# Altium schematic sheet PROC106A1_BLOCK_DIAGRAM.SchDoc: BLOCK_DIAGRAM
size 431 x 279 mm; Date: Not shown in title block; ApprovedBy: Not shown in title block; CheckedBy: Not shown in title block; Author: Not shown in title block; CompanyName: Not shown in title block; DrawnBy: Antony/Anand Ram; Engineer: Not shown in title block; Organization: Not shown in title block; Address1: Not shown in title block; Address2: Not shown in title block; Address3: Not shown in title block; Address4: Not shown in title block; DocumentNumber: 1; Revision: Use project parameter SCH_Rev; SheetNumber: 1; SheetTotal: 12; PageSetup: Record=PageOptions¦CenterHorizontal=True¦CenterVertical=True¦PrintScale=1.00¦XCorrection=1.00¦YCorrection=1.00¦PrintKind=0¦BorderSize=5000000¦LeftOffset=0¦BottomOffset=0¦Orientation=2¦PaperLength=1000¦PaperWidth=1000¦Scale=100¦PaperSource=15¦PrintQuality=600¦MediaType=1¦DitherType=10¦PaperKind=Letter¦PrintScaleMode=1
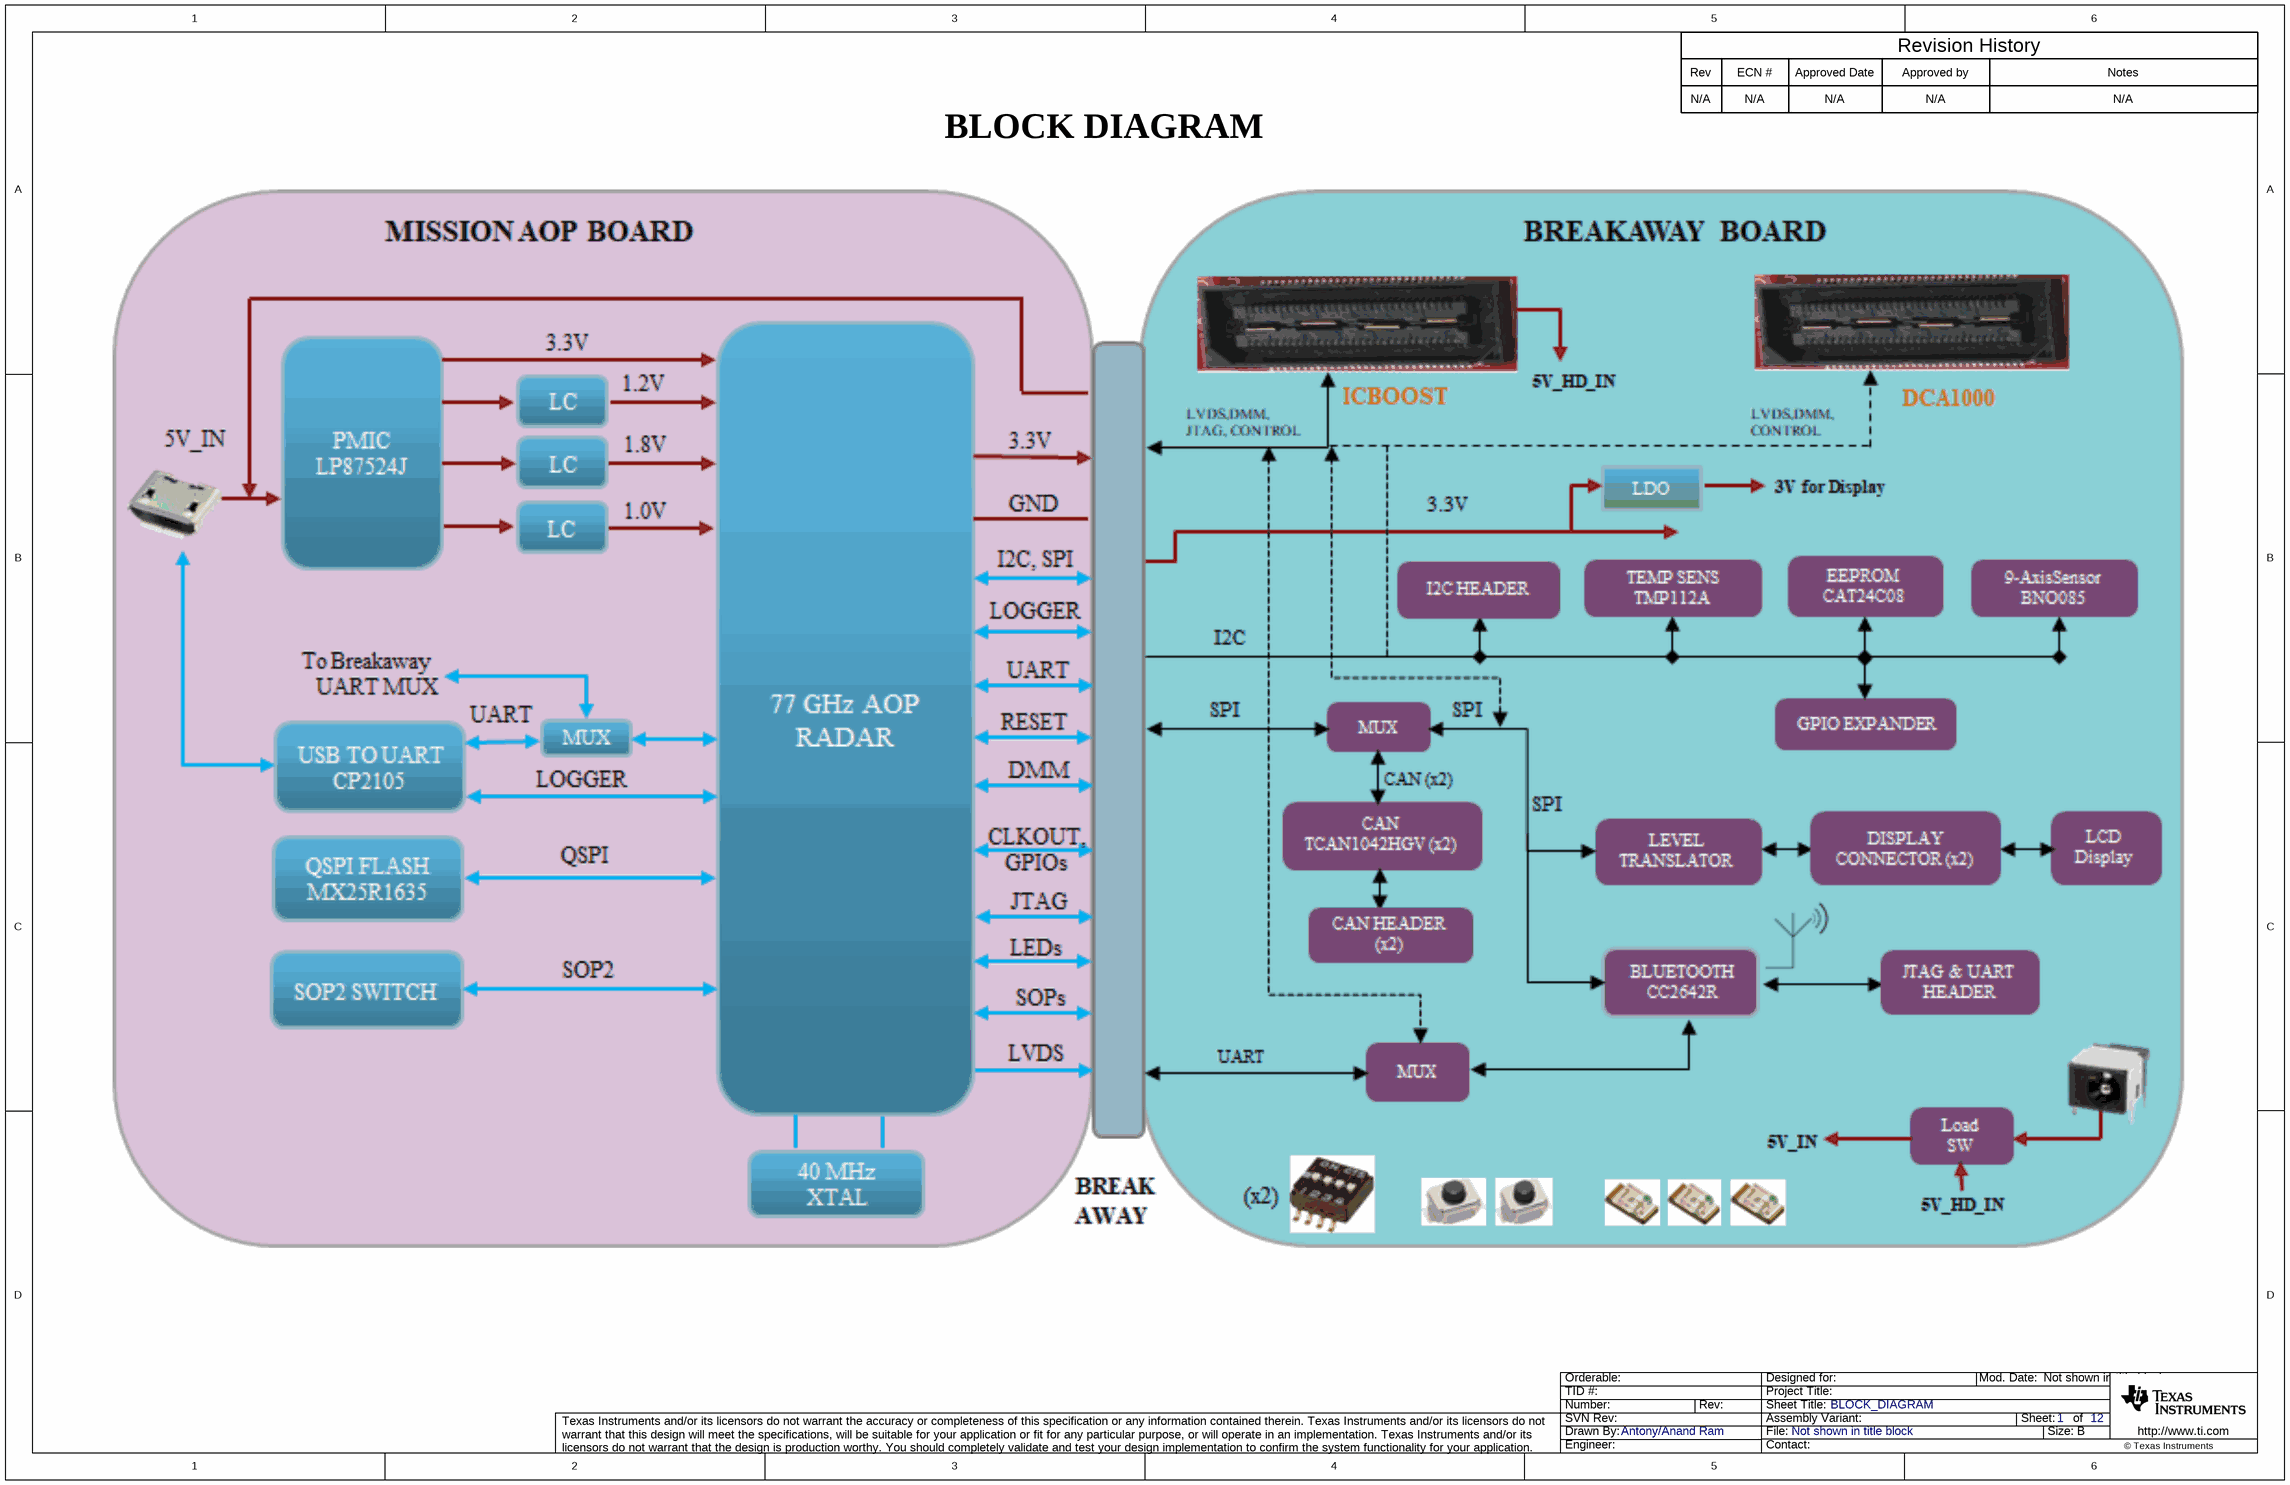
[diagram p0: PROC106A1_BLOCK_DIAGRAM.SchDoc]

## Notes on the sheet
- Rev
- N/A
- ECN #
- Approved Date
- Approved by
- Revision History
- Notes
- BLOCK DIAGRAM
